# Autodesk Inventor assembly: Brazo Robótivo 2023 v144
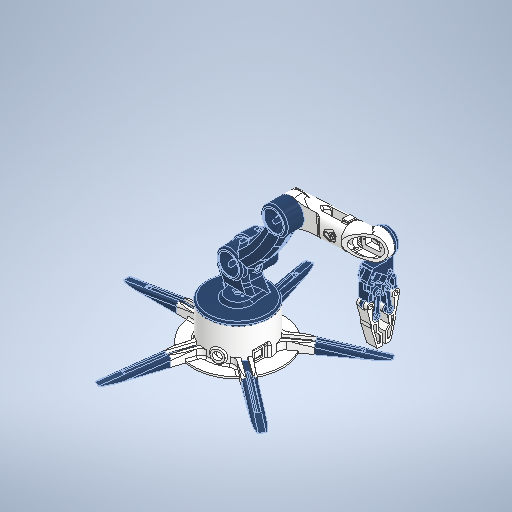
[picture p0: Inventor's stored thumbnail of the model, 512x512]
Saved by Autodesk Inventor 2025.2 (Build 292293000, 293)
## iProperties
Created: 2024-04
Part Number: Brazo Robótivo 2023 v144
Document SubType Name: Assembly
Designer: Gustavo Sousa
Sending System: Autodesk Translation Framework v12.20.1.177
Preprocessor: ST-DEVELOPER v20
Title: Brazo Robtivo 2023 v144.step
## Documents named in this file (22)
- C:\Users\lucas\OneDrive\Documentos\Documentos\Gustavo\Mozangao\Projeto Base (5140)\braco_robotico\Brazo Robótivo 2023 v144\Brazo Robótivo 2023 v144\Brazo Robótivo 2023 v144.iam
- C:\Users\lucas\OneDrive\Documentos\Documentos\Gustavo\Mozangao\Projeto Base (5140)\braco_robotico\Brazo Robótivo 2023 v144\Brazo Robótivo 2023 v144\Engranaje1.ipt
- C:\Users\lucas\OneDrive\Documentos\Documentos\Gustavo\Mozangao\Projeto Base (5140)\braco_robotico\Brazo Robótivo 2023 v144\Brazo Robótivo 2023 v144\Engranaje2.ipt
- C:\Users\lucas\OneDrive\Documentos\Documentos\Gustavo\Mozangao\Projeto Base (5140)\braco_robotico\Brazo Robótivo 2023 v144\Brazo Robótivo 2023 v144\Barra2.ipt
- C:\Users\lucas\OneDrive\Documentos\Documentos\Gustavo\Mozangao\Projeto Base (5140)\braco_robotico\Brazo Robótivo 2023 v144\Brazo Robótivo 2023 v144\Barra1.ipt
- C:\Users\lucas\OneDrive\Documentos\Documentos\Gustavo\Mozangao\Projeto Base (5140)\braco_robotico\Brazo Robótivo 2023 v144\Brazo Robótivo 2023 v144\Pinza1.ipt
- C:\Users\lucas\OneDrive\Documentos\Documentos\Gustavo\Mozangao\Projeto Base (5140)\braco_robotico\Brazo Robótivo 2023 v144\Brazo Robótivo 2023 v144\Pinza2.ipt
- C:\Users\lucas\OneDrive\Documentos\Documentos\Gustavo\Mozangao\Projeto Base (5140)\braco_robotico\Brazo Robótivo 2023 v144\Brazo Robótivo 2023 v144\Base de la garra.ipt
- C:\Users\lucas\OneDrive\Documentos\Documentos\Gustavo\Mozangao\Projeto Base (5140)\braco_robotico\Brazo Robótivo 2023 v144\Brazo Robótivo 2023 v144\Base (1) (1).ipt
- C:\Users\lucas\OneDrive\Documentos\Documentos\Gustavo\Mozangao\Projeto Base (5140)\braco_robotico\Brazo Robótivo 2023 v144\Brazo Robótivo 2023 v144\Antebrazo (4).ipt
- C:\Users\lucas\OneDrive\Documentos\Documentos\Gustavo\Mozangao\Projeto Base (5140)\braco_robotico\Brazo Robótivo 2023 v144\Brazo Robótivo 2023 v144\Muñeca.ipt
- C:\Users\lucas\OneDrive\Documentos\Documentos\Gustavo\Mozangao\Projeto Base (5140)\braco_robotico\Brazo Robótivo 2023 v144\Brazo Robótivo 2023 v144\Eje Central.ipt
- C:\Users\lucas\OneDrive\Documentos\Documentos\Gustavo\Mozangao\Projeto Base (5140)\braco_robotico\Brazo Robótivo 2023 v144\Brazo Robótivo 2023 v144\Tapa Eje.ipt
- C:\Users\lucas\OneDrive\Documentos\Documentos\Gustavo\Mozangao\Projeto Base (5140)\braco_robotico\Brazo Robótivo 2023 v144\Brazo Robótivo 2023 v144\Tapa Base.ipt
- C:\Users\lucas\OneDrive\Documentos\Documentos\Gustavo\Mozangao\Projeto Base (5140)\braco_robotico\Brazo Robótivo 2023 v144\Brazo Robótivo 2023 v144\Brazo.ipt
- C:\Users\lucas\OneDrive\Documentos\Documentos\Gustavo\Mozangao\Projeto Base (5140)\braco_robotico\Brazo Robótivo 2023 v144\Brazo Robótivo 2023 v144\Tapa garra.ipt
- C:\Users\lucas\OneDrive\Documentos\Documentos\Gustavo\Mozangao\Projeto Base (5140)\braco_robotico\Brazo Robótivo 2023 v144\Brazo Robótivo 2023 v144\Pata1.ipt
- C:\Users\lucas\OneDrive\Documentos\Documentos\Gustavo\Mozangao\Projeto Base (5140)\braco_robotico\Brazo Robótivo 2023 v144\Brazo Robótivo 2023 v144\Pata2.ipt
- C:\Users\lucas\OneDrive\Documentos\Documentos\Gustavo\Mozangao\Projeto Base (5140)\braco_robotico\Brazo Robótivo 2023 v144\Brazo Robótivo 2023 v144\Pata3.ipt
- C:\Users\lucas\OneDrive\Documentos\Documentos\Gustavo\Mozangao\Projeto Base (5140)\braco_robotico\Brazo Robótivo 2023 v144\Brazo Robótivo 2023 v144\Pata4.ipt
- C:\Users\lucas\OneDrive\Documentos\Documentos\Gustavo\Mozangao\Projeto Base (5140)\braco_robotico\Brazo Robótivo 2023 v144\Brazo Robótivo 2023 v144\Pata5.ipt
- C:\Users\lucas\OneDrive\Documentos\Documentos\Gustavo\Mozangao\Projeto Base (5140)\braco_robotico\Brazo Robótivo 2023 v144\Brazo Robótivo 2023 v144\Seguro de servomotor.ipt
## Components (21 placed, 21 different names)
1. Engranaje1:1 — Coincidente:24, Coincidente:25, Inserir:10
2. Engranaje2:1 — Coincidente:22, Coincidente:23, Inserir:11
3. Barra2:1 — Inserir:8, Coincidente:27
4. Barra1:1 — Inserir:9, Coincidente:26
5. Pinza1:1 — Inserir:10, Coincidente:26
6. Pinza2:1 — Inserir:11, Coincidente:27
7. Base de la garra:1 — Inserir:6, Coincidente:21, Inserir:8, Inserir:9, Inserir:12
8. Base (1) (1):1
9. Antebrazo (4):1 — Inserir:2, Inserir:4
10. Muñeca:1 — Inserir:5, Inserir:12
11. Eje Central:1 — Inserir:1, Coincidente:19, Coincidente:20, Inserir:2
12. Tapa Eje:1 — Coincidente:19, Coincidente:20
13. Tapa Base:1 — Coincidente:17, Coincidente:18
14. Brazo:1 — Inserir:3, Inserir:4, Inserir:5
15. Tapa garra:1 — Inserir:6, Coincidente:21, Coincidente:22, Coincidente:23, Coincidente:24, Coincidente:25
16. Pata1:1 — Coincidente:9, Coincidente:10
17. Pata2:1 — Coincidente:11, Coincidente:12
18. Pata3:1 — Coincidente:15, Coincidente:16
19. Pata4:1 — Coincidente:13, Coincidente:14
20. Pata5:1 — Coincidente:7, Coincidente:8
21. Seguro de servomotor:1 — Inserir:3
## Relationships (32: Mate 21, Insert 11)
- Coincidente:7 [Mate]: Pata5:1
- Coincidente:8 [Mate]: Pata5:1
- Coincidente:9 [Mate]: Pata1:1
- Coincidente:10 [Mate]: Pata1:1
- Coincidente:11 [Mate]: Pata2:1
- Coincidente:12 [Mate]: Pata2:1
- Coincidente:13 [Mate]: Pata4:1
- Coincidente:14 [Mate]: Pata4:1
- Coincidente:15 [Mate]: Pata3:1
- Coincidente:16 [Mate]: Pata3:1
- Coincidente:17 [Mate]: Tapa Base:1
- Coincidente:18 [Mate]: Tapa Base:1
- Inserir:1: Eje Central:1
- Coincidente:19 [Mate]: Eje Central:1 ↔ Tapa Eje:1
- Coincidente:20 [Mate]: Eje Central:1 ↔ Tapa Eje:1
- Inserir:2: Antebrazo (4):1 ↔ Eje Central:1
- Inserir:3: Brazo:1 ↔ Seguro de servomotor:1
- Inserir:4: Antebrazo (4):1 ↔ Brazo:1
- Inserir:5: Muñeca:1 ↔ Brazo:1
- Inserir:6: Base de la garra:1 ↔ Tapa garra:1
- Coincidente:21 [Mate]: Base de la garra:1 ↔ Tapa garra:1
- Inserir:8: Barra2:1 ↔ Base de la garra:1
- Inserir:9: Barra1:1 ↔ Base de la garra:1
- Coincidente:22 [Mate]: Engranaje2:1 ↔ Tapa garra:1
- Coincidente:23 [Mate]: Engranaje2:1 ↔ Tapa garra:1
- Coincidente:24 [Mate]: Engranaje1:1 ↔ Tapa garra:1
- Coincidente:25 [Mate]: Engranaje1:1 ↔ Tapa garra:1
- Inserir:10: Engranaje1:1 ↔ Pinza1:1
- Coincidente:26 [Mate]: Barra1:1 ↔ Pinza1:1
- Inserir:11: Engranaje2:1 ↔ Pinza2:1
- Coincidente:27 [Mate]: Barra2:1 ↔ Pinza2:1
- Inserir:12: Base de la garra:1 ↔ Muñeca:1
